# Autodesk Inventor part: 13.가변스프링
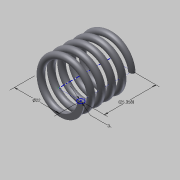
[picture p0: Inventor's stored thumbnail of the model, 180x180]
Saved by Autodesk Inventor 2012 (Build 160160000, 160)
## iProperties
Created: 2014-12
Part Number: 13.가변스프링
Material: 탄소강
Document SubType Name: Modeling
Designer: HOME
Density: 7.87 g/cm^3
Mass: 18.7435 g
Surface Area: 32.4191 cm^2
Volume: 2.38164 cm^3
Author: HOME
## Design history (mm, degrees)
sketch "스케치1"
  geometry: L1 (0, 0)-(11, 0); L2 (11, 0)-(11, 25.358); L3 (11, 25.358)-(0, 25.358); L4 (0, 25.358)-(0, 0); C1 r 1.5 at (11, 0); 1 further point
  constraints: 8 end point, 2 coincident, 2 parallel, 1 centre point, 1 horizontal, 1 perpendicular
  dimensions: "d0" = 22 diameter of L2 L4; "d1" = 25.35829 distance of L1.end L2.end (derived); "d2" = 3 diameter of C1
feature "코일1" pitch "d3" = 10; turns "d5" = 5; dims "d4" = 25.35829 (= d1), "d6" = 0, angle "d7" = 90 deg, angle "d8" = 90 deg, "d9" = 0, "d10" = 0
sketch "스케치2"
  geometry: L1 (-12.5, 0)-(-9.5, 0) reference; 1 further point
  constraints: 1 horizontal alignment
extrude "돌출1" cut sketch "스케치2" stored distance "d11" = 10; taper "d12" = 0 deg
node "작업 평면1"
sketch "스케치3"
  geometry: L1 (-9.5, 0)-(-12.5, 0) reference; 1 further point
  constraints: 1 horizontal alignment
extrude "돌출2" cut sketch "스케치3" stored distance "d13" = 10; taper "d14" = 0 deg
node "솔리드1"
node "절단 모서리 투영1"
node "절단 모서리 투영2"
